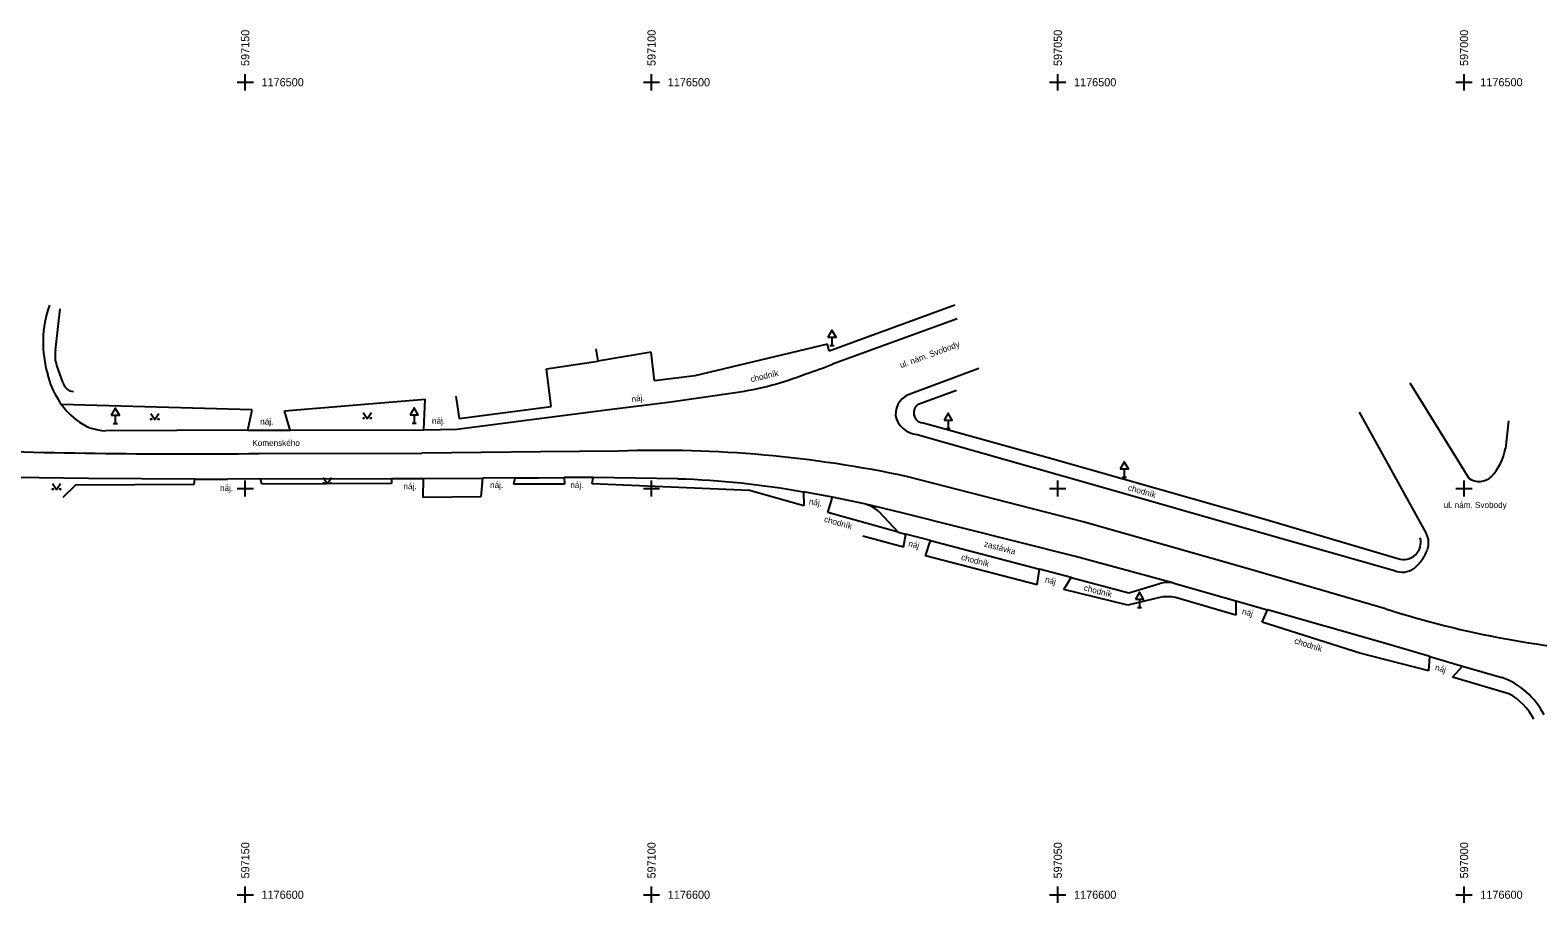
# Model space of a CAD drawing. Extents: x -598160 to -596067, y -1177005 to -1176344.
# Drawn here: x -597176.5 to -596990.9, y -1176601 to -1176493.6 of the extents above; entities that cross this region are included whole.
import ezdxf

# ---------------------------------------------------------------- set-up
doc = ezdxf.new("R2010")
doc.units = 0
for name, color, linetype in [('bez obruby', 7, 'Continuous'), ('budova', 7, 'Continuous'), ('dopravní značení svislé', 7, 'Continuous'), ('hektametrová síť', 7, 'Continuous'), ('obruba +0 cm', 7, 'Continuous'), ('obruba +12 cm', 7, 'Continuous'), ('obruba +3 cm', 7, 'Continuous'), ('popis ploch', 7, 'Continuous'), ('rozhraní ploch', 7, 'Continuous'), ('vodorovné značení', 7, 'Continuous'), ('zeleň', 7, 'Continuous')]:
    doc.layers.add(name, color=color, linetype=linetype)

msp = doc.modelspace()

# ---------------------------------------------------------------- linework, layer by layer
at = {"layer": 'bez obruby'}
for p, q in [((-597069.01, -1176553.05), (-597073.8, -1176551.89)), ((-597047.84, -1176558.39), (-597069.01, -1176553.05)), ((-597035.71, -1176561.66), (-597047.84, -1176558.39))]:
    msp.add_line(p, q, dxfattribs=at)
at = {"layer": 'budova'}
for p, q in [((-597106.85, -1176532.83), (-597106.62, -1176534.32)), ((-597112.92, -1176535.28), (-597106.62, -1176534.32)), ((-597112.34, -1176539.89), (-597112.92, -1176535.28)), ((-597124.09, -1176538.65), (-597123.67, -1176541.39)), ((-597123.67, -1176541.39), (-597112.34, -1176539.89))]:
    msp.add_line(p, q, dxfattribs=at)
at = {"layer": 'dopravní značení svislé'}
for p, q in [((-597078.04, -1176532.39), (-597077.54, -1176532.39)), ((-597077.79, -1176531.37), (-597077.79, -1176532.39)), ((-597166.24, -1176542.01), (-597165.74, -1176542.01)), ((-597165.99, -1176540.99), (-597165.99, -1176542.01)), ((-597129.46, -1176541.95), (-597128.96, -1176541.95)), ((-597129.21, -1176540.93), (-597129.21, -1176541.95)), ((-597063.48, -1176541.61), (-597063.48, -1176542.63)), ((-597063.73, -1176542.63), (-597063.23, -1176542.63)), ((-597041.81, -1176547.6), (-597041.81, -1176548.62)), ((-597042.06, -1176548.62), (-597041.56, -1176548.62)), ((-597039.94, -1176563.61), (-597039.94, -1176564.63)), ((-597040.19, -1176564.63), (-597039.69, -1176564.63))]:
    msp.add_line(p, q, dxfattribs=at)
for points in [[(-597078.29, -1176531.37), (-597077.29, -1176531.37), (-597077.79, -1176530.51)], [(-597166.49, -1176540.99), (-597165.49, -1176540.99), (-597165.99, -1176540.13)], [(-597129.71, -1176540.93), (-597128.71, -1176540.93), (-597129.21, -1176540.07)], [(-597063.98, -1176541.61), (-597062.98, -1176541.61), (-597063.48, -1176540.75)], [(-597042.31, -1176547.6), (-597041.31, -1176547.6), (-597041.81, -1176546.74)], [(-597040.44, -1176563.61), (-597039.44, -1176563.61), (-597039.94, -1176562.75)]]:
    msp.add_lwpolyline(points, close=True, dxfattribs=at)
at = {"layer": 'hektametrová síť'}
for p, q in [((-597150, -1176501), (-597150, -1176499)), ((-597100, -1176501), (-597100, -1176499)), ((-597050, -1176501), (-597050, -1176499)), ((-597000, -1176501), (-597000, -1176499)), ((-597151, -1176500), (-597149, -1176500)), ((-597101, -1176500), (-597099, -1176500)), ((-597051, -1176500), (-597049, -1176500)), ((-597001, -1176500), (-596999, -1176500)), ((-597150, -1176551), (-597150, -1176549)), ((-597100, -1176551), (-597100, -1176549)), ((-597050, -1176551), (-597050, -1176549)), ((-597000, -1176551), (-597000, -1176549)), ((-597151, -1176550), (-597149, -1176550)), ((-597101, -1176550), (-597099, -1176550)), ((-597051, -1176550), (-597049, -1176550)), ((-597001, -1176550), (-596999, -1176550)), ((-597150, -1176601), (-597150, -1176599)), ((-597100, -1176601), (-597100, -1176599)), ((-597050, -1176601), (-597050, -1176599)), ((-597000, -1176601), (-597000, -1176599)), ((-597151, -1176600), (-597149, -1176600)), ((-597101, -1176600), (-597099, -1176600)), ((-597051, -1176600), (-597049, -1176600)), ((-597001, -1176600), (-596999, -1176600))]:
    msp.add_line(p, q, dxfattribs=at)
at = {"layer": 'obruba +0 cm'}
for p, q in [((-597149.7, -1176542.83), (-597144.49, -1176542.83)), ((-597128, -1176542.79), (-597123.94, -1176542.69)), ((-597156.22, -1176548.84), (-597152.18, -1176548.86)), ((-597116.79, -1176548.7), (-597120.82, -1176548.73)), ((-597107.2, -1176548.65), (-597110.73, -1176548.64)), ((-597004.2, -1176570.68), (-597000.21, -1176571.85))]:
    msp.add_line(p, q, dxfattribs=at)
at = {"layer": 'obruba +12 cm'}
for p, q in [((-597062.39, -1176529.13), (-597077.72, -1176534.72)), ((-597173.21, -1176534.85), (-597172.47, -1176536.9)), ((-597059.7, -1176535.24), (-597067.97, -1176538.3)), ((-597171.62, -1176537.98), (-597171.14, -1176538.05)), ((-597097.62, -1176539.33), (-597089.68, -1176538.19)), ((-597006.66, -1176536.99), (-596999.41, -1176548.72)), ((-597123.94, -1176542.69), (-597114.14, -1176541.43)), ((-597114.14, -1176541.43), (-597105.55, -1176540.34)), ((-597004.64, -1176555.55), (-597012.86, -1176540.59)), ((-596994.52, -1176541.69), (-596994.91, -1176545.07)), ((-597149.7, -1176542.83), (-597167.17, -1176542.89)), ((-597067.3, -1176543.34), (-597045.65, -1176549.51)), ((-597169.28, -1176548.79), (-597178.41, -1176548.66)), ((-597156.22, -1176548.84), (-597169.28, -1176548.79)), ((-597148.14, -1176548.81), (-597132.01, -1176548.77)), ((-597128.06, -1176548.77), (-597120.82, -1176548.73)), ((-597116.79, -1176548.7), (-597113.91, -1176548.69)), ((-597113.91, -1176548.69), (-597110.73, -1176548.64)), ((-597096.74, -1176548.83), (-597107.2, -1176548.65)), ((-597045.65, -1176549.51), (-597025.03, -1176555.41)), ((-597073.8, -1176551.89), (-597077.71, -1176551.07)), ((-597072.03, -1176552.85), (-597069.66, -1176555.38)), ((-597069.66, -1176555.38), (-597068.7, -1176555.64)), ((-597065.67, -1176556.41), (-597052.27, -1176559.95)), ((-597025.03, -1176555.41), (-597008.57, -1176560.11)), ((-597048.37, -1176560.97), (-597041.27, -1176562.84)), ((-597041.27, -1176562.84), (-597037.44, -1176561.71)), ((-597035.71, -1176561.66), (-597028.07, -1176563.83)), ((-597010.07, -1176568.96), (-597024.17, -1176564.95)), ((-597004.2, -1176570.68), (-597010.07, -1176568.96)), ((-597000.21, -1176571.85), (-596995.37, -1176573.25))]:
    msp.add_line(p, q, dxfattribs=at)
for centre, radius, start, end in [((-597160.92, -1176532.03), 13.96, 160.7133, 196.4793), ((-597169.85, -1176533.67), 3.56, 168.6227, 199.2886), ((-597120.82, -1176419.38), 123.13, 288.8604, 290.4912), ((-597164.46, -1176533.65), 10.13, 193.3364, 231.1371), ((-597095.43, -1176498.92), 39.69, 278.3326, 291.2912), ((-597170.71, -1176536.39), 1.83, 196.1328, 240.2753), ((-597067.24, -1176540.93), 2.73, 105.5019, 181.4404), ((-597167.03, -1176536.92), 5.97, 230.6896, 268.6128), ((-597067.12, -1176540.45), 2.9, 191.0269, 266.5102), ((-597001.96, -1176543.72), 7.18, 318.0794, 349.1898), ((-597100.24, -1176658.14), 109.36, 80.0164, 88.1662), ((-596998.13, -1176546.98), 2.16, 233.7436, 314.4568), ((-597074.72, -1176555.69), 3.91, 46.6187, 76.4329), ((-597006.76, -1176556.68), 2.4, 339.3484, 28.1645), ((-597009.95, -1176555.41), 5.84, 323.2693, 338.6925), ((-597007.61, -1176557.73), 2.57, 248.0056, 304.3093), ((-597036.49, -1176564.64), 3.08, 75.3573, 107.9536), ((-596998.59, -1176582.15), 9.47, 27.0233, 70.093)]:
    msp.add_arc(centre, radius, start, end, dxfattribs=at)
at = {"layer": 'obruba +3 cm'}
for p, q in [((-597105.55, -1176540.34), (-597097.62, -1176539.33)), ((-597148.14, -1176548.81), (-597152.18, -1176548.86)), ((-597132.01, -1176548.77), (-597128.06, -1176548.77)), ((-597077.71, -1176551.07), (-597081.28, -1176550.43)), ((-597065.67, -1176556.41), (-597068.7, -1176555.64)), ((-597048.37, -1176560.97), (-597052.27, -1176559.95)), ((-597028.07, -1176563.83), (-597024.17, -1176564.95))]:
    msp.add_line(p, q, dxfattribs=at)
msp.add_arc((-597009.95, -1176555.41), 5.84, 310.4661, 323.2693, dxfattribs=at)
at = {"layer": 'popis ploch'}
msp.add_line((-597173.34, -1176532.97), (-597172.78, -1176527.87), dxfattribs=at)
at = {"layer": 'rozhraní ploch'}
for p, q in [((-597062.68, -1176527.43), (-597078.14, -1176533.09)), ((-597078.35, -1176532.23), (-597094.68, -1176536.14)), ((-597078.14, -1176533.09), (-597078.35, -1176532.23)), ((-597100.06, -1176533.21), (-597106.62, -1176534.32)), ((-597099.64, -1176536.75), (-597100.06, -1176533.21)), ((-597094.68, -1176536.14), (-597099.64, -1176536.75)), ((-597067.17, -1176539.64), (-597062.46, -1176537.91)), ((-597149.15, -1176540.33), (-597172.61, -1176539.66)), ((-597145.17, -1176540.45), (-597127.86, -1176539.01)), ((-597128, -1176542.79), (-597127.86, -1176539.01)), ((-597149.7, -1176542.83), (-597149.15, -1176540.33)), ((-597144.49, -1176542.83), (-597145.17, -1176540.45)), ((-597050.62, -1176546.38), (-597066.69, -1176541.91)), ((-597144.49, -1176542.83), (-597128, -1176542.79)), ((-597024.66, -1176553.79), (-597050.62, -1176546.38)), ((-597170.88, -1176549.58), (-597172.45, -1176551.11)), ((-597156.3, -1176549.5), (-597170.88, -1176549.58)), ((-597156.3, -1176549.5), (-597156.22, -1176548.84)), ((-597147.94, -1176549.47), (-597148.14, -1176548.81)), ((-597131.98, -1176549.39), (-597147.94, -1176549.47)), ((-597132.01, -1176548.77), (-597131.98, -1176549.39)), ((-597128.11, -1176551.12), (-597128.06, -1176548.77)), ((-597120.82, -1176548.73), (-597120.99, -1176551.04)), ((-597116.93, -1176549.47), (-597116.79, -1176548.7)), ((-597110.7, -1176549.47), (-597116.93, -1176549.47)), ((-597110.73, -1176548.64), (-597110.7, -1176549.47)), ((-597107.29, -1176549.43), (-597107.2, -1176548.65)), ((-597087.93, -1176550.26), (-597107.29, -1176549.43)), ((-597120.99, -1176551.04), (-597128.11, -1176551.12)), ((-597081.27, -1176552.14), (-597087.93, -1176550.26)), ((-597081.28, -1176550.43), (-597081.27, -1176552.14)), ((-597078.3, -1176552.97), (-597077.71, -1176551.07)), ((-597069.66, -1176555.38), (-597078.3, -1176552.97)), ((-597008.13, -1176558.64), (-597024.66, -1176553.79)), ((-597068.99, -1176557.24), (-597074, -1176555.85)), ((-597068.99, -1176557.24), (-597068.7, -1176555.64)), ((-597066.3, -1176558.29), (-597065.67, -1176556.41)), ((-597052.54, -1176561.86), (-597066.3, -1176558.29)), ((-597052.54, -1176561.86), (-597052.27, -1176559.95)), ((-597049.26, -1176562.42), (-597048.37, -1176560.97)), ((-597041.39, -1176564.35), (-597049.26, -1176562.42)), ((-597037.27, -1176563.38), (-597041.39, -1176564.35)), ((-597028.07, -1176565.61), (-597035.52, -1176563.43)), ((-597028.07, -1176563.83), (-597028.07, -1176565.61)), ((-597024.84, -1176566.47), (-597024.17, -1176564.95)), ((-597012.84, -1176570.29), (-597024.84, -1176566.47)), ((-597004.35, -1176572.45), (-597012.84, -1176570.29)), ((-597004.35, -1176572.45), (-597004.2, -1176570.68)), ((-597001.41, -1176573.23), (-597000.21, -1176571.85)), ((-596994.5, -1176575.26), (-597001.41, -1176573.23))]:
    msp.add_line(p, q, dxfattribs=at)
for centre, radius, start, end in [((-597066.48, -1176540.68), 1.25, 123.4208, 260.4583), ((-597007.45, -1176556.62), 2.13, 251.2465, 15.0861), ((-597036.53, -1176567.96), 4.64, 77.4835, 99.2433), ((-596997.77, -1176581.53), 7.07, 26.2607, 62.4477)]:
    msp.add_arc(centre, radius, start, end, dxfattribs=at)
at = {"layer": 'vodorovné značení'}
for p, q in [((-597148.3, -1176545.7), (-597128.27, -1176545.64)), ((-597113.67, -1176545.47), (-597128.27, -1176545.64)), ((-597104.05, -1176545.39), (-597113.67, -1176545.47)), ((-597046.87, -1176554.1), (-597068.44, -1176548.55)), ((-597026.68, -1176559.83), (-597046.87, -1176554.1)), ((-597009.65, -1176564.8), (-597026.68, -1176559.83))]:
    msp.add_line(p, q, dxfattribs=at)
for centre, radius, start, end in [((-597157.11, -1175699.52), 846.22, 267.8679, 270.59634), ((-597099.04, -1176691.17), 145.86, 77.8898, 91.968), ((-596972.88, -1176449.39), 121.13, 252.3299, 266.7503)]:
    msp.add_arc(centre, radius, start, end, dxfattribs=at)
at = {"layer": 'zeleň'}
for points in [[(-597161.63, -1176540.77), (-597161.13, -1176541.52), (-597160.63, -1176540.77)], [(-597135.48, -1176540.65), (-597134.98, -1176541.4), (-597134.48, -1176540.65)], [(-597173.73, -1176549.39), (-597173.23, -1176550.14), (-597172.73, -1176549.39)], [(-597140.39, -1176548.65), (-597139.89, -1176549.4), (-597139.39, -1176548.65)]]:
    msp.add_lwpolyline(points, dxfattribs=at)
for centre in [(-597161.58, -1176541.47), (-597160.68, -1176541.47), (-597135.43, -1176541.35), (-597134.53, -1176541.35), (-597140.34, -1176549.35), (-597139.44, -1176549.35), (-597173.68, -1176550.09), (-597172.78, -1176550.09)]:
    msp.add_circle(centre, 0.05, dxfattribs=at)

# ---------------------------------------------------------------- texts
at = {"layer": 'hektametrová síť'}
for s, p in [('597150', (-597149.5, -1176498)), ('597100', (-597099.5, -1176498)), ('597050', (-597049.5, -1176498)), ('597000', (-596999.5, -1176498)), ('597150', (-597149.5, -1176598)), ('597100', (-597099.5, -1176598)), ('597050', (-597049.5, -1176598)), ('597000', (-596999.5, -1176598))]:
    msp.add_text(s, height=1, rotation=90, dxfattribs=at).set_placement(p)
for s, p in [('1176500', (-597148, -1176500.5)), ('1176500', (-597098, -1176500.5)), ('1176500', (-597048, -1176500.5)), ('1176500', (-596998, -1176500.5)), ('1176600', (-597148, -1176600.5)), ('1176600', (-597098, -1176600.5)), ('1176600', (-597048, -1176600.5)), ('1176600', (-596998, -1176600.5))]:
    msp.add_text(s, height=1, dxfattribs=at).set_placement(p)
at = {"layer": 'popis ploch'}
for s, rotation, p in [('ul. nám. Svobody', 20.0341, (-597069.28, -1176535.19)), ('chodník', 13.4652, (-597087.72, -1176536.94)), ('náj.', 7.2584, (-597102.42, -1176539.37)), ('náj.', 1.4109, (-597127.02, -1176542.06)), ('náj.', 359.7164, (-597153.11, -1176550.3)), ('náj.', 0.4265, (-597119.86, -1176549.95)), ('náj.', 0.4265, (-597109.99, -1176549.95)), ('náj.', 349.8364, (-597080.67, -1176551.93)), ('chodník', 344.0692, (-597041.42, -1176550.21)), ('chodník', 344.4143, (-597078.82, -1176554.09)), ('náj', 345.3432, (-597068.45, -1176557.09)), ('zastávka', 345.2017, (-597059.13, -1176557.14)), ('chodník', 345.4554, (-597061.95, -1176558.78)), ('náj', 345.3432, (-597051.63, -1176561.52)), ('chodník', 345.4554, (-597046.85, -1176562.54)), ('náj', 343.977, (-597027.38, -1176565.42)), ('chodník', 342.342, (-597020.95, -1176569.05)), ('náj', 343.6571, (-597003.63, -1176572.33))]:
    msp.add_text(s, height=0.75, rotation=rotation, dxfattribs=at).set_placement(p)
for s, p in [('náj.', (-597148.16, -1176542.13)), ('Komenského', (-597149.13, -1176544.77)), ('náj.', (-597130.53, -1176550.1)), ('ul. nám. Svobody', (-597002.5, -1176552.4))]:
    msp.add_text(s, height=0.75, dxfattribs=at).set_placement(p)

doc.saveas('drawing.dxf')
